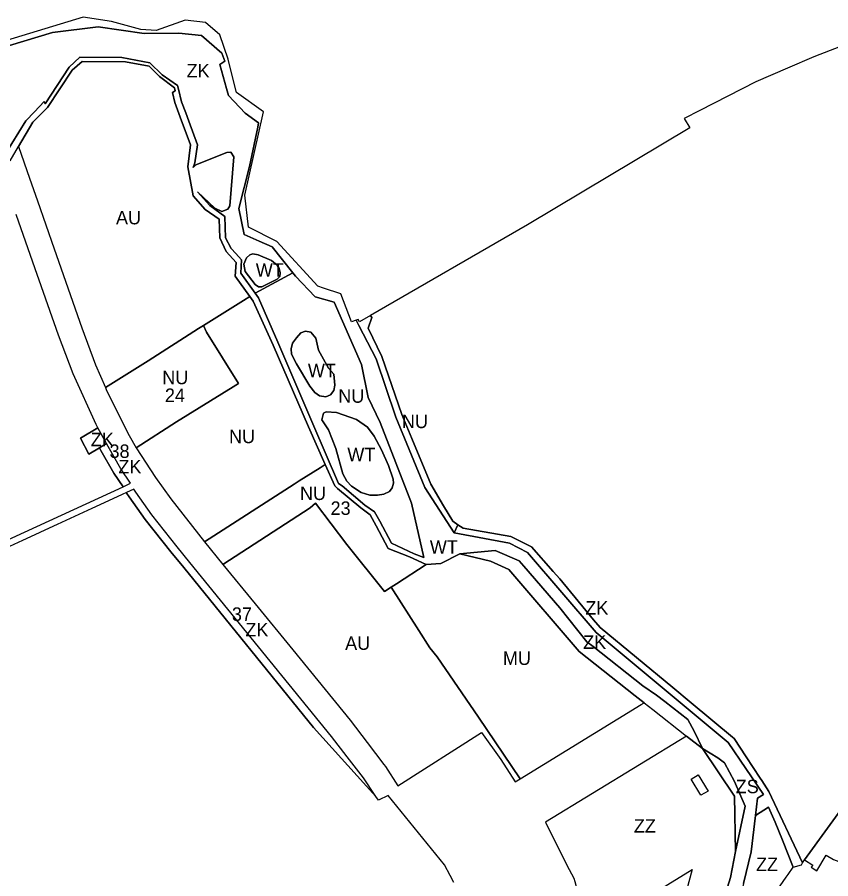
# Model space of a CAD drawing. Extents: x -522079 to -518833, y -1142398 to -1139961.
# Drawn here: x -520990 to -520386, y -1140733 to -1140093 of the extents above; entities that cross this region are included whole.
import ezdxf

# ---------------------------------------------------------------- set-up
doc = ezdxf.new("R2010")
doc.units = 0
for name, color, linetype in [('90640013', 7, 'Continuous'), ('90660013', 7, 'Continuous'), ('90670013', 7, 'Continuous'), ('90710013', 7, 'Continuous'), ('90710023', 7, 'Continuous'), ('90730013', 7, 'Continuous'), ('90730023', 7, 'Continuous'), ('90750013', 7, 'Continuous'), ('90830013', 7, 'Continuous'), ('ID_navrh', 7, 'Continuous')]:
    doc.layers.add(name, color=color, linetype=linetype)

msp = doc.modelspace()

# ---------------------------------------------------------------- linework, layer by layer
at = {"layer": '90640013'}
for points in [[(-520442.27, -1140685.74), (-520440.71, -1140673.04), (-520436.48, -1140670.33), (-520462.54, -1140631.68), (-520560.63, -1140549.81), (-520611.7, -1140490.5), (-520625.05, -1140483.49), (-520666, -1140475.86), (-520687.78, -1140442.24), (-520709.46, -1140390.03), (-520724.04, -1140346.68), (-520736.79, -1140321.94), (-520738.8, -1140318.04), (-520742.16, -1140319.24), (-520750.13, -1140298.42), (-520763.01, -1140294.16), (-520767.33, -1140292.73), (-520797.63, -1140259.52), (-520818.83, -1140248.97), (-520821.47, -1140225.09), (-520807.65, -1140163.22), (-520827.76, -1140148.83), (-520832.38, -1140130.38), (-520833.95, -1140124.09), (-520840.13, -1140106.03), (-520850.56, -1140096.88), (-520865.88, -1140095.27), (-520887.39, -1140102.82), (-520898.59, -1140102.13), (-520920.41, -1140096.1), (-520941.45, -1140093.01), (-520998.41, -1140110.24)], [(-520996.26, -1140113.95), (-520964.33, -1140104.24), (-520930.39, -1140100.03), (-520896.13, -1140105.14), (-520870.57, -1140104.77), (-520853.61, -1140106.69), (-520838.47, -1140119.76), (-520836.28, -1140125.74), (-520840.13, -1140128.04), (-520837.6, -1140136.97), (-520834.99, -1140146), (-520833.53, -1140151.04), (-520821.16, -1140164.16), (-520811.24, -1140171.54), (-520811.93, -1140174.77), (-520818.11, -1140203.91), (-520825.87, -1140235.03), (-520821.91, -1140254.48), (-520810.93, -1140259.32), (-520801.15, -1140263.64), (-520785.74, -1140282.9), (-520783.73, -1140285.25), (-520769.34, -1140300.61), (-520755.22, -1140304.57), (-520734.8, -1140350.95), (-520729.88, -1140375.38), (-520720.9, -1140393.9), (-520697.67, -1140453.81), (-520688.63, -1140494.17), (-520695.64, -1140491.57), (-520712.6, -1140483.62), (-520721.21, -1140467.33), (-520725.07, -1140460.42), (-520732.44, -1140455.44), (-520749.19, -1140441.04), (-520751.81, -1140439.25), (-520770.87, -1140395.08), (-520797.01, -1140334.21), (-520811.33, -1140301.33), (-520813.67, -1140297.99), (-520824.45, -1140283.03), (-520824.03, -1140273.06), (-520828.22, -1140268.46), (-520831.58, -1140264.76), (-520835.7, -1140256.78), (-520836.21, -1140241.05), (-520847.4, -1140232.82), (-520856.59, -1140222.67), (-520843.85, -1140234.81), (-520838.62, -1140237.3), (-520834.17, -1140235.54), (-520832.49, -1140233.14), (-520829.57, -1140196.57), (-520831.74, -1140193.15), (-520834.84, -1140193.48), (-520857.8, -1140202.58), (-520859.91, -1140204.51), (-520858.48, -1140201.26), (-520856.72, -1140187.75), (-520863, -1140170.11), (-520865.3, -1140164.1), (-520868.43, -1140155.94), (-520870.79, -1140146.36), (-520871.38, -1140143.8), (-520882.74, -1140135.78), (-520891.9, -1140126.87), (-520912.67, -1140122.89), (-520943.89, -1140122.58), (-520951.79, -1140130), (-520969.72, -1140157.28), (-520970.51, -1140155.67), (-520977.56, -1140163.28), (-520984.14, -1140169.84), (-520999.73, -1140195.29)], [(-520995.82, -1140199.62), (-520989.57, -1140189.1), (-520978.85, -1140171.05), (-520967.99, -1140160), (-520949.73, -1140132.35), (-520942.17, -1140125.91), (-520910.05, -1140126.02), (-520892.49, -1140129.42), (-520884.78, -1140137.14), (-520873.63, -1140145.32), (-520873.12, -1140147.75), (-520875.21, -1140149), (-520873.34, -1140156.37), (-520869.38, -1140167.25), (-520861.9, -1140187.8), (-520863.77, -1140204.01), (-520859.87, -1140225.61), (-520850.88, -1140235.71), (-520840.6, -1140242.88), (-520840.04, -1140256.81), (-520835.3, -1140267.04), (-520827.93, -1140275.18), (-520828.6, -1140285.19), (-520817.67, -1140300.36), (-520815.23, -1140303.96), (-520800.48, -1140336.51), (-520774.21, -1140397.13), (-520761.78, -1140425.25), (-520754.76, -1140441.12), (-520752.54, -1140443.09), (-520735.34, -1140457.3), (-520728.4, -1140462.65), (-520724, -1140470.78), (-520714.97, -1140487.48), (-520699.14, -1140493.81), (-520686.89, -1140499.45), (-520675.92, -1140498.77), (-520661.91, -1140491.42), (-520635.69, -1140488.94), (-520617.72, -1140496.63), (-520614.24, -1140500.69), (-520587.68, -1140531.64), (-520567.56, -1140556.74), (-520562.84, -1140560.36), (-520525.93, -1140589.59), (-520515.8, -1140596.49), (-520509.5, -1140601.29), (-520492.51, -1140614.6), (-520487.78, -1140623.27), (-520481.74, -1140636.06), (-520470.21, -1140643.01), (-520465.4, -1140646.75), (-520457.96, -1140660.67), (-520449.96, -1140678.96), (-520457.2, -1140712.56), (-520460.77, -1140732), (-520466.36, -1140749.44)], [(-520451.15, -1140736.24), (-520445.6, -1140712.87), (-520442.27, -1140685.74)]]:
    msp.add_lwpolyline(points, dxfattribs=at)
for points in [[(-520822.29, -1140276.46), (-520821.31, -1140281.75), (-520813.83, -1140291.57), (-520811.29, -1140293.11), (-520808.84, -1140293.29), (-520797.46, -1140287.61), (-520795.38, -1140285.61), (-520795.15, -1140282.87), (-520796.05, -1140279.66), (-520797.56, -1140277.1), (-520801.58, -1140273.72), (-520811.67, -1140269.37), (-520815.5, -1140268.8), (-520817.84, -1140269.53), (-520820.3, -1140271.64)], [(-520785.95, -1140335.16), (-520787.17, -1140339.26), (-520786.73, -1140343.23), (-520783.16, -1140350.46), (-520773.17, -1140366.91), (-520769.43, -1140371.66), (-520765.93, -1140374.29), (-520761.4, -1140374.89), (-520757.78, -1140373.33), (-520755.28, -1140370.09), (-520754.64, -1140366.29), (-520755.29, -1140358.03), (-520759.43, -1140353.7), (-520766.65, -1140340.21), (-520768.74, -1140331.28), (-520772.48, -1140326.88), (-520776.36, -1140326.07), (-520779.88, -1140327.47), (-520783.19, -1140331.06)], [(-520764.21, -1140391.88), (-520759.4, -1140399.48), (-520753.83, -1140413.22), (-520748.72, -1140432.03), (-520745.71, -1140437.58), (-520742.3, -1140441.21), (-520735.07, -1140445.99), (-520728.76, -1140447.85), (-520722.88, -1140447.92), (-520718.16, -1140447.28), (-520714.17, -1140445.14), (-520712.14, -1140442.41), (-520711.04, -1140439.09), (-520711.41, -1140436.09), (-520714.9, -1140426), (-520719.87, -1140414.3), (-520725.51, -1140404.14), (-520730.43, -1140397.36), (-520738.54, -1140391.69), (-520753.32, -1140386.65), (-520761.05, -1140386.08), (-520763.05, -1140387.08)]]:
    msp.add_lwpolyline(points, close=True, dxfattribs=at)
at = {"layer": '90660013'}
msp.add_lwpolyline([(-520481.74, -1140636.06), (-520457.81, -1140671.57), (-520457.2, -1140712.56), (-520449.96, -1140678.96), (-520457.96, -1140660.67), (-520465.4, -1140646.75), (-520470.21, -1140643.01), (-520481.74, -1140636.06)], dxfattribs=at)
at = {"layer": '90670013'}
for points in [[(-520481.74, -1140636.06), (-520493.55, -1140626.8), (-520598.21, -1140690.89), (-520586.97, -1140713.22), (-520580.64, -1140725.97), (-520577.29, -1140732.42), (-520576.44, -1140734.91), (-520575.25, -1140739.5), (-520574.04, -1140754.01), (-520550.23, -1140761.11), (-520547.81, -1140761.83), (-520528.59, -1140750.29), (-520489.4, -1140725.83), (-520495.27, -1140747.98), (-520479.24, -1140748.79), (-520466.36, -1140749.44), (-520460.77, -1140732), (-520457.2, -1140712.56), (-520457.81, -1140671.57), (-520481.74, -1140636.06)], [(-520490.13, -1140658.74), (-520484.85, -1140655.59), (-520477.53, -1140667.74), (-520482.81, -1140670.82), (-520490.13, -1140658.74)], [(-520371.84, -1140671.62), (-520371.84, -1140671.63), (-520405.96, -1140718.81), (-520399.85, -1140722.62), (-520400.9, -1140724.3), (-520396.68, -1140726.94), (-520389.9, -1140715.22), (-520384.29, -1140718.48), (-520375.15, -1140722.06), (-520369.41, -1140698.76), (-520364.42, -1140661.36), (-520371.84, -1140671.62)], [(-520442.27, -1140685.74), (-520445.6, -1140712.87), (-520451.15, -1140736.24), (-520453.26, -1140745.12), (-520466.39, -1140772.32), (-520448.2, -1140773.61), (-520446.34, -1140770.88), (-520445.76, -1140770.03), (-520442.66, -1140765.49), (-520442.65, -1140765.47), (-520441.56, -1140761.77), (-520440.36, -1140762.11), (-520434.44, -1140753.41), (-520431.9, -1140749.57), (-520421.72, -1140734.81), (-520419.44, -1140731.56), (-520418.13, -1140729.68), (-520414.39, -1140724.32), (-520422.23, -1140704.1), (-520427.81, -1140690.88), (-520432.59, -1140679.54), (-520442.27, -1140685.74)]]:
    msp.add_lwpolyline(points, dxfattribs=at)
at = {"layer": '90710013'}
for points in [[(-520785.74, -1140282.9), (-520801.15, -1140263.64), (-520810.93, -1140259.32), (-520821.91, -1140254.48), (-520825.87, -1140235.03), (-520818.11, -1140203.91), (-520811.93, -1140174.77), (-520811.24, -1140171.54), (-520821.16, -1140164.16), (-520833.53, -1140151.04), (-520834.99, -1140146), (-520837.6, -1140136.97), (-520840.13, -1140128.04), (-520836.28, -1140125.74), (-520838.47, -1140119.76), (-520853.61, -1140106.69), (-520870.57, -1140104.77), (-520896.13, -1140105.14), (-520930.39, -1140100.03), (-520964.33, -1140104.24), (-520996.26, -1140113.95)], [(-520999.73, -1140195.29), (-520984.14, -1140169.84), (-520977.56, -1140163.28), (-520970.51, -1140155.67), (-520969.72, -1140157.28), (-520951.79, -1140130), (-520943.89, -1140122.58), (-520912.67, -1140122.89), (-520891.9, -1140126.87), (-520882.74, -1140135.78), (-520871.38, -1140143.8), (-520870.79, -1140146.36), (-520868.43, -1140155.94), (-520865.3, -1140164.1), (-520863, -1140170.11), (-520856.72, -1140187.75), (-520858.48, -1140201.26), (-520859.91, -1140204.51), (-520857.8, -1140202.58), (-520834.84, -1140193.48), (-520831.74, -1140193.15), (-520829.57, -1140196.57), (-520832.49, -1140233.14), (-520834.17, -1140235.54), (-520838.62, -1140237.3), (-520843.85, -1140234.81), (-520856.59, -1140222.67), (-520847.4, -1140232.82), (-520836.21, -1140241.05), (-520835.7, -1140256.78), (-520831.58, -1140264.76), (-520828.22, -1140268.46), (-520824.03, -1140273.06), (-520824.45, -1140283.03), (-520813.67, -1140297.99), (-520785.74, -1140282.9)], [(-520663.2, -1140469.86), (-520666, -1140475.86), (-520625.05, -1140483.49), (-520611.7, -1140490.5), (-520560.63, -1140549.81), (-520462.54, -1140631.68), (-520436.48, -1140670.33), (-520440.71, -1140673.04), (-520442.27, -1140685.74), (-520432.59, -1140679.54), (-520427.81, -1140690.88), (-520422.23, -1140704.1), (-520414.39, -1140724.32), (-520408.23, -1140722.45), (-520407.37, -1140721.08), (-520432.32, -1140668.06), (-520437.69, -1140659.73), (-520438.76, -1140658.07), (-520449.35, -1140642.33), (-520458.26, -1140628.64), (-520459.31, -1140627.54), (-520490.09, -1140602.11), (-520503.8, -1140590.78), (-520557.7, -1140546.26), (-520562.49, -1140540.48), (-520587.65, -1140510.13), (-520592.52, -1140504.62), (-520608.7, -1140486.32), (-520623.97, -1140478.75), (-520659.41, -1140472.47), (-520663.2, -1140469.86)], [(-520525.02, -1140602.15), (-520518.65, -1140607.14), (-520493.55, -1140626.8), (-520481.74, -1140636.06), (-520487.78, -1140623.27), (-520492.51, -1140614.6), (-520509.5, -1140601.29), (-520515.8, -1140596.49), (-520525.93, -1140589.59), (-520562.84, -1140560.36), (-520567.56, -1140556.74), (-520587.68, -1140531.64), (-520614.24, -1140500.69), (-520617.72, -1140496.63), (-520635.69, -1140488.94), (-520661.91, -1140491.42), (-520639.11, -1140496.92), (-520625.42, -1140503.23), (-520573.29, -1140563.98), (-520531.68, -1140596.93), (-520525.02, -1140602.15)]]:
    msp.add_lwpolyline(points, dxfattribs=at)
for points in [[(-520822.29, -1140276.46), (-520820.3, -1140271.64), (-520817.84, -1140269.53), (-520815.5, -1140268.8), (-520811.67, -1140269.37), (-520801.58, -1140273.72), (-520797.56, -1140277.1), (-520796.05, -1140279.66), (-520795.15, -1140282.87), (-520795.38, -1140285.61), (-520797.46, -1140287.61), (-520808.84, -1140293.29), (-520811.29, -1140293.11), (-520813.83, -1140291.57), (-520821.31, -1140281.75)], [(-520924.28, -1140409.64), (-520930.52, -1140398.04), (-520943.46, -1140405.56), (-520937.19, -1140417.44), (-520929.42, -1140412.75)]]:
    msp.add_lwpolyline(points, close=True, dxfattribs=at)
at = {"layer": '90710023'}
msp.add_lwpolyline([(-520924.28, -1140409.64), (-520929.42, -1140412.75), (-520928.3, -1140414.82), (-520918.68, -1140431.5), (-520911.89, -1140441.66), (-520906.37, -1140439.12), (-520913.58, -1140428.33), (-520923.06, -1140411.9), (-520924.28, -1140409.64)], dxfattribs=at)
msp.add_lwpolyline([(-520909.31, -1140446.06), (-520908.96, -1140446.68), (-520907.36, -1140449.12), (-520895.38, -1140466.06), (-520876.33, -1140490.04), (-520866.87, -1140501.66), (-520770.37, -1140620.36), (-520724.12, -1140671.61), (-520733.42, -1140657.97), (-520745.42, -1140642.26), (-520757.18, -1140627.06), (-520765.71, -1140616.57), (-520862.22, -1140497.87), (-520871.65, -1140486.28), (-520890.58, -1140462.46), (-520902.4, -1140445.74), (-520903.84, -1140443.54)], close=True, dxfattribs=at)
at = {"layer": '90730013'}
for points in [[(-520785.74, -1140282.9), (-520813.67, -1140297.99), (-520811.33, -1140301.33), (-520797.01, -1140334.21), (-520770.87, -1140395.08), (-520751.81, -1140439.25), (-520749.19, -1140441.04), (-520732.44, -1140455.44), (-520725.07, -1140460.42), (-520721.21, -1140467.33), (-520712.6, -1140483.62), (-520695.64, -1140491.57), (-520688.63, -1140494.17), (-520697.67, -1140453.81), (-520720.9, -1140393.9), (-520729.88, -1140375.38), (-520734.8, -1140350.95), (-520755.22, -1140304.57), (-520769.34, -1140300.61), (-520783.73, -1140285.25), (-520785.74, -1140282.9)], [(-520817.67, -1140300.36), (-520822.46, -1140303.46), (-520852.13, -1140321.93), (-520849.95, -1140326.96), (-520826.19, -1140365.01), (-520830.07, -1140367.42), (-520872.15, -1140393.54), (-520902.19, -1140412.67), (-520887.82, -1140434.78), (-520876.46, -1140450.75), (-520851.49, -1140482.48), (-520784.75, -1140439.67), (-520781.06, -1140437.3), (-520765.49, -1140427.57), (-520761.78, -1140425.25), (-520774.21, -1140397.13), (-520800.48, -1140336.51), (-520815.23, -1140303.96), (-520817.67, -1140300.36)], [(-520663.2, -1140469.86), (-520666.98, -1140467.24), (-520673.87, -1140455.8), (-520683.48, -1140439.85), (-520697.54, -1140405.82), (-520704.93, -1140387.92), (-520719.64, -1140344.89), (-520729.96, -1140323.84), (-520727.12, -1140316.09), (-520728.21, -1140314.51), (-520736.37, -1140319.22), (-520737.2, -1140317.47), (-520738.8, -1140318.04), (-520736.79, -1140321.94), (-520724.04, -1140346.68), (-520709.46, -1140390.03), (-520687.78, -1140442.24), (-520666, -1140475.86), (-520663.2, -1140469.86)]]:
    msp.add_lwpolyline(points, dxfattribs=at)
for points in [[(-520785.95, -1140335.16), (-520783.19, -1140331.06), (-520779.88, -1140327.47), (-520776.36, -1140326.07), (-520772.48, -1140326.88), (-520768.74, -1140331.28), (-520766.65, -1140340.21), (-520759.43, -1140353.7), (-520755.29, -1140358.03), (-520754.64, -1140366.29), (-520755.28, -1140370.09), (-520757.78, -1140373.33), (-520761.4, -1140374.89), (-520765.93, -1140374.29), (-520769.43, -1140371.66), (-520773.17, -1140366.91), (-520783.16, -1140350.46), (-520786.73, -1140343.23), (-520787.17, -1140339.26)], [(-520764.21, -1140391.88), (-520763.05, -1140387.08), (-520761.05, -1140386.08), (-520753.32, -1140386.65), (-520738.54, -1140391.69), (-520730.43, -1140397.36), (-520725.51, -1140404.14), (-520719.87, -1140414.3), (-520714.9, -1140426), (-520711.41, -1140436.09), (-520711.04, -1140439.09), (-520712.14, -1140442.41), (-520714.17, -1140445.14), (-520718.16, -1140447.28), (-520722.88, -1140447.92), (-520728.76, -1140447.85), (-520735.07, -1140445.99), (-520742.3, -1140441.21), (-520745.71, -1140437.58), (-520748.72, -1140432.03), (-520753.83, -1140413.22), (-520759.4, -1140399.48)]]:
    msp.add_lwpolyline(points, close=True, dxfattribs=at)
at = {"layer": '90730023'}
for points in [[(-520925.04, -1140368.05), (-520924.44, -1140369.44), (-520915.77, -1140387.04), (-520907.24, -1140403.74), (-520902.19, -1140412.67), (-520872.15, -1140393.54), (-520830.07, -1140367.42), (-520826.19, -1140365.01), (-520849.95, -1140326.96), (-520852.13, -1140321.93), (-520855.89, -1140324.19), (-520893.13, -1140348.26), (-520925.04, -1140368.05)], [(-520761.78, -1140425.25), (-520765.49, -1140427.57), (-520781.06, -1140437.3), (-520784.75, -1140439.67), (-520851.49, -1140482.48), (-520837.71, -1140499.35), (-520772.84, -1140457.31), (-520769.04, -1140453.82), (-520745.68, -1140484.57), (-520717.71, -1140519.42), (-520712.75, -1140516.21), (-520708.82, -1140513.67), (-520686.89, -1140499.45), (-520699.14, -1140493.81), (-520714.97, -1140487.48), (-520724, -1140470.78), (-520728.4, -1140462.65), (-520735.34, -1140457.3), (-520752.54, -1140443.09), (-520754.76, -1140441.12), (-520761.78, -1140425.25)]]:
    msp.add_lwpolyline(points, dxfattribs=at)
at = {"layer": '90750013'}
for points in [[(-520359.48, -1140107), (-520398.93, -1140122.43), (-520418.53, -1140130.92), (-520442, -1140141.08), (-520483.64, -1140162.33), (-520495.34, -1140168.3), (-520491.09, -1140175.17), (-520611.62, -1140247.2), (-520728.21, -1140314.51), (-520727.12, -1140316.09), (-520729.96, -1140323.84), (-520719.64, -1140344.89), (-520704.93, -1140387.92), (-520697.54, -1140405.82), (-520683.48, -1140439.85), (-520673.87, -1140455.8), (-520666.98, -1140467.24), (-520663.2, -1140469.86), (-520659.41, -1140472.47), (-520623.97, -1140478.75), (-520608.7, -1140486.32), (-520592.52, -1140504.62), (-520587.65, -1140510.13), (-520562.49, -1140540.48), (-520557.7, -1140546.26), (-520503.8, -1140590.78), (-520490.09, -1140602.11), (-520459.31, -1140627.54), (-520458.26, -1140628.64), (-520449.35, -1140642.33), (-520438.76, -1140658.07), (-520437.69, -1140659.73), (-520432.32, -1140668.06), (-520407.37, -1140721.08), (-520405.96, -1140718.81), (-520371.84, -1140671.63)], [(-520925.04, -1140368.05), (-520893.13, -1140348.26), (-520855.89, -1140324.19), (-520852.13, -1140321.93), (-520822.46, -1140303.46), (-520817.67, -1140300.36), (-520828.6, -1140285.19), (-520827.93, -1140275.18), (-520835.3, -1140267.04), (-520840.04, -1140256.81), (-520840.6, -1140242.88), (-520850.88, -1140235.71), (-520859.87, -1140225.61), (-520863.77, -1140204.01), (-520861.9, -1140187.8), (-520869.38, -1140167.25), (-520873.34, -1140156.37), (-520875.21, -1140149), (-520873.12, -1140147.75), (-520873.63, -1140145.32), (-520884.78, -1140137.14), (-520892.49, -1140129.42), (-520910.05, -1140126.02), (-520942.17, -1140125.91), (-520949.73, -1140132.35), (-520967.99, -1140160), (-520978.85, -1140171.05), (-520989.57, -1140189.1), (-520981.4, -1140212.45), (-520975.5, -1140229.32), (-520963.03, -1140264.99), (-520942.5, -1140323.7), (-520932.27, -1140351.12), (-520925.04, -1140368.05)], [(-521031.07, -1140496.4), (-520911.89, -1140441.66), (-520918.68, -1140431.5), (-520928.3, -1140414.82), (-520929.42, -1140412.75), (-520937.19, -1140417.44), (-520943.46, -1140405.56), (-520930.52, -1140398.04), (-520931.92, -1140395.43), (-520948.85, -1140357.77), (-520959.74, -1140329.07), (-520978.89, -1140274.79), (-520991.34, -1140239.5)], [(-520666.3, -1140735.71), (-520669.12, -1140730.36), (-520673.31, -1140722.41), (-520715.02, -1140671.04), (-520722.11, -1140674.56), (-520724.12, -1140671.61), (-520770.37, -1140620.36), (-520866.87, -1140501.66), (-520876.33, -1140490.04), (-520895.38, -1140466.06), (-520907.36, -1140449.12), (-520908.96, -1140446.68), (-520909.31, -1140446.06), (-521038.29, -1140505.39)]]:
    msp.add_lwpolyline(points, dxfattribs=at)
msp.add_lwpolyline([(-520631.48, -1140644.23), (-520620.66, -1140660.83), (-520617.05, -1140658.61), (-520648.02, -1140612.72), (-520678.73, -1140568), (-520684.19, -1140561.2), (-520692.27, -1140548.47), (-520712.75, -1140516.21), (-520717.71, -1140519.42), (-520745.68, -1140484.57), (-520769.04, -1140453.82), (-520772.84, -1140457.31), (-520837.71, -1140499.35), (-520813.81, -1140528.62), (-520785.9, -1140562.81), (-520743.28, -1140615.01), (-520730.64, -1140631.58), (-520718.15, -1140647.9), (-520717.09, -1140649.55), (-520707.94, -1140663.79), (-520645.69, -1140624.14)], close=True, dxfattribs=at)
at = {"layer": '90830013'}
msp.add_lwpolyline([(-520525.02, -1140602.15), (-520531.68, -1140596.93), (-520573.29, -1140563.98), (-520625.42, -1140503.23), (-520639.11, -1140496.92), (-520661.91, -1140491.42), (-520675.92, -1140498.77), (-520686.89, -1140499.45), (-520708.82, -1140513.67), (-520712.75, -1140516.21), (-520692.27, -1140548.47), (-520684.19, -1140561.2), (-520678.73, -1140568), (-520648.02, -1140612.72), (-520617.05, -1140658.61), (-520527.15, -1140603.46), (-520525.02, -1140602.15)], dxfattribs=at)

# ---------------------------------------------------------------- texts
at = {"layer": '90640013'}
msp.add_text('WT', height=10, dxfattribs=at).set_placement((-520813.33, -1140285.76))
for rotation, p in [(0, (-520774.65, -1140360.33)), (360, (-520745.35, -1140422.71)), (360, (-520684.1, -1140491.45))]:
    msp.add_text('WT', height=10, rotation=rotation, dxfattribs=at).set_placement(p)
at = {"layer": '90660013'}
msp.add_text('ZS', height=10, rotation=0, dxfattribs=at).set_placement((-520456.99, -1140669.27))
at = {"layer": '90670013'}
for rotation, p in [(0, (-520532.65, -1140698.56)), (360, (-520441.96, -1140727.15))]:
    msp.add_text('ZZ', height=10, rotation=rotation, dxfattribs=at).set_placement(p)
at = {"layer": '90710013'}
for rotation, p in [(0, (-520864.7, -1140137.72)), (360, (-520935.9, -1140411.62)), (360, (-520568.66, -1140536.64)), (0, (-520570.27, -1140562.14))]:
    msp.add_text('ZK', height=10, rotation=rotation, dxfattribs=at).set_placement(p)
at = {"layer": '90710023'}
for rotation, p in [(360, (-520915.35, -1140431.74)), (0, (-520821.06, -1140552.83))]:
    msp.add_text('ZK', height=10, rotation=rotation, dxfattribs=at).set_placement(p)
at = {"layer": '90730013'}
for p in [(-520752.09, -1140379.33), (-520704.8, -1140398.15), (-520833.19, -1140409.34)]:
    msp.add_text('NU', height=10, rotation=360, dxfattribs=at).set_placement(p)
at = {"layer": '90730023'}
for rotation, p in [(360, (-520882.77, -1140365.57)), (0, (-520780.52, -1140451.57))]:
    msp.add_text('NU', height=10, rotation=rotation, dxfattribs=at).set_placement(p)
at = {"layer": '90750013'}
msp.add_text('AU', height=10, dxfattribs=at).set_placement((-520917.12, -1140246.84))
msp.add_text('AU', height=10, rotation=360, dxfattribs=at).set_placement((-520746.98, -1140562.84))
at = {"layer": '90830013'}
msp.add_text('MU', height=10, rotation=360, dxfattribs=at).set_placement((-520629.86, -1140574.04))
at = {"layer": 'ID_navrh'}
for s, rotation, p in [('24', 0, (-520880.8, -1140378.75)), ('38', 360, (-520921.91, -1140420.3)), ('23', 0, (-520757.8, -1140462.6)), ('37', 360, (-520831.06, -1140541.29))]:
    msp.add_text(s, height=10, rotation=rotation, dxfattribs=at).set_placement(p)

doc.saveas('drawing.dxf')
